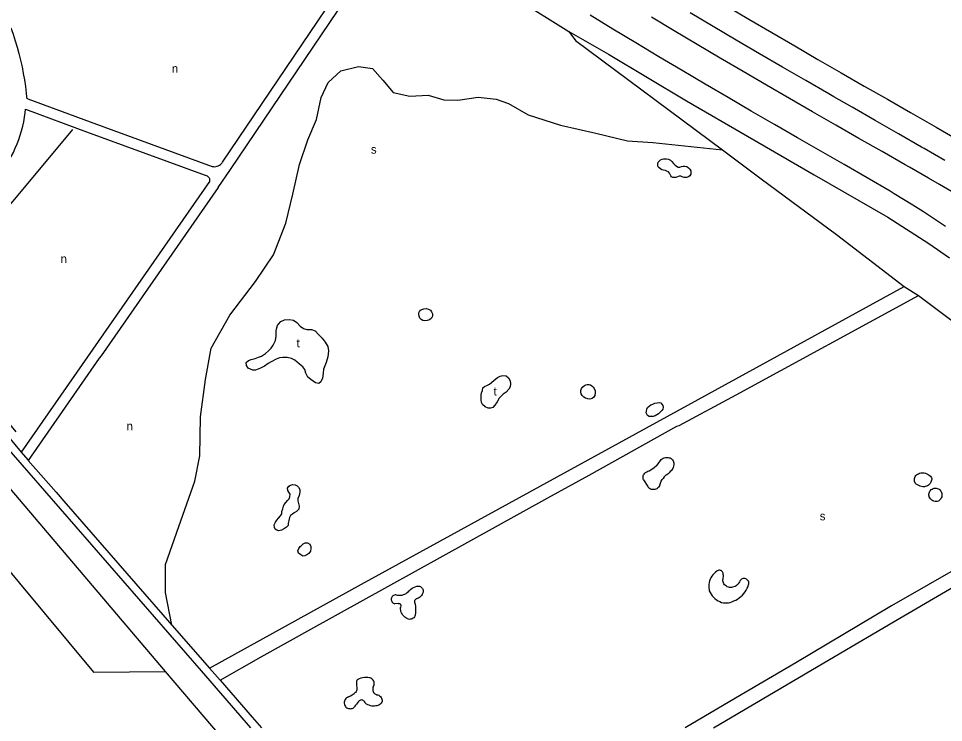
# Model space of a CAD drawing. Extents: x 156066 to 157805, y 383432 to 385631.
# Drawn here: x 156957.2 to 157390.3, y 384502.5 to 384832 of the extents above; entities that cross this region are included whole.
import ezdxf

# ---------------------------------------------------------------- set-up
doc = ezdxf.new("R2010")
doc.units = 0
doc.layers.add('BLT_Basislijn', color=7, linetype='Continuous')
doc.layers.add('BLT_Centroide', color=7, linetype='Continuous')

msp = doc.modelspace()

# ---------------------------------------------------------------- linework, layer by layer
at = {"layer": 'BLT_Basislijn'}
for p, q in [((157052.72, 384764.82), (157125.74, 384872.85)), ((157056.42, 384761.37), (157132.55, 384873.99)), ((156961.42, 384794.55), (156961.61, 384794.45)), ((157050.76, 384752.88), (157056.42, 384761.37)), ((157046.66, 384755.73), (156958.49, 384629.07)), ((157050.76, 384752.88), (156995.97, 384674.17)), ((157371.83, 384706.57), (157378.55, 384702.32)), ((156919.84, 384675.3), (156958.49, 384629.07)), ((156995.97, 384674.17), (156995.06, 384673.02)), ((156995.06, 384673.02), (156961.82, 384625.1)), ((156945.58, 384638.24), (157042.7, 384526.65)), ((156958.49, 384629.07), (156961.59, 384625.36)), ((156961.59, 384625.36), (156961.82, 384625.1)), ((156961.82, 384625.1), (156974.79, 384610.24)), ((157483.49, 384624.52), (157365.92, 384557.05)), ((157249.83, 384616.05), (157251.8, 384612.89)), ((156974.79, 384610.24), (156978.39, 384606.11)), ((156978.39, 384606.11), (157029.07, 384548.06)), ((157287.16, 384571.65), (157286.96, 384569.46)), ((157134.89, 384558.16), (157133.42, 384558.1)), ((157136.18, 384557.2), (157136.13, 384556.24)), ((157029.07, 384548.06), (157046.66, 384527.91)), ((157052.19, 384495.7), (157026.05, 384526.43)), ((157042.7, 384526.65), (157065.9, 384500)), ((157046.66, 384527.91), (157051.61, 384522.24)), ((157051.61, 384522.24), (157066.67, 384504.99)), ((157066.67, 384504.99), (157071.06, 384500))]:
    msp.add_line(p, q, dxfattribs=at)
for points in [[(157127.03, 384882.25), (157165.83, 384856.66), (157214.85, 384825.93)], [(157288.29, 384838.07), (157299.07, 384831.73), (157309.87, 384825.41), (157320.68, 384819.13), (157331.5, 384812.86), (157342.34, 384806.62), (157353.18, 384800.39), (157364.03, 384794.18), (157374.88, 384787.97), (157385.73, 384781.77), (157386.91, 384781.09), (157396.58, 384775.56)], [(157391.26, 384734.71), (157386.09, 384738.11), (157380.89, 384741.46), (157375.97, 384744.58), (157367.23, 384749.96), (157365.32, 384751.12), (157354.55, 384757.47), (157343.7, 384763.69), (157332.84, 384769.92), (157321.99, 384776.15), (157311.14, 384782.41), (157300.3, 384788.68), (157289.47, 384794.99), (157278.65, 384801.32), (157267.85, 384807.68), (157257.06, 384814.09), (157246.29, 384820.53), (157235.54, 384827.01), (157224.81, 384833.55)], [(157390.87, 384765.58), (157381.21, 384771.11), (157380.03, 384771.78), (157369.17, 384777.98), (157358.32, 384784.19), (157347.46, 384790.42), (157339, 384795.27), (157336.6, 384796.65), (157325.75, 384802.9), (157314.91, 384809.18), (157304.08, 384815.48), (157293.25, 384821.81), (157282.44, 384828.17), (157271.65, 384834.57)], [(157404.89, 384744.78), (157394.08, 384751.05), (157388.35, 384754.34), (157383.23, 384757.27), (157374.32, 384762.37), (157372.38, 384763.48), (157361.53, 384769.68), (157350.68, 384775.89), (157339.84, 384782.1), (157329, 384788.33), (157318.17, 384794.57), (157307.35, 384800.84), (157296.55, 384807.12), (157285.76, 384813.43), (157274.99, 384819.78), (157264.25, 384826.16), (157253.52, 384832.57)], [(156953.67, 384827.54), (156954.73, 384824.58), (156955.71, 384821.59), (156956.62, 384818.58), (156957.45, 384815.54), (156958.21, 384812.48), (156958.88, 384809.41), (156959.48, 384806.32), (156960, 384803.22), (156960.44, 384800.1), (156960.8, 384796.97), (156960.96, 384795.3)], [(157214.85, 384825.93), (157217.99, 384821.75), (157286.78, 384770.55)], [(157214.85, 384825.93), (157233.41, 384815.26), (157270.01, 384793.38), (157298.55, 384776.89), (157329.77, 384758.86), (157364.24, 384738.95), (157383.47, 384726.72), (157393.03, 384719.99)], [(157029.07, 384548.06), (157026.12, 384563.36), (157026.12, 384576.4), (157032.27, 384594.24), (157039.76, 384615.52), (157042.16, 384627.37), (157042.46, 384645.5), (157044.71, 384663.04), (157047.41, 384677.73), (157056.1, 384693.17), (157068.24, 384708.91), (157076.64, 384721.35), (157082.33, 384736.19), (157085.63, 384749.83), (157088.78, 384763.62), (157092.68, 384775.17), (157096.72, 384784.76), (157098.97, 384794.95), (157102.12, 384802), (157108.12, 384807.54), (157116.36, 384809.49), (157122.96, 384808.59), (157127.75, 384803.2), (157132.55, 384797.35), (157140.5, 384795.7), (157149.04, 384796.15), (157156.39, 384793.9), (157162.83, 384793.75), (157172.42, 384795.1), (157180.82, 384794.2), (157186.66, 384792.26), (157195.81, 384786.86), (157210.95, 384782.06), (157227.44, 384778.31), (157242.28, 384774.72), (157254.12, 384773.97), (157286.78, 384770.55)], [(156960.96, 384795.3), (156961.03, 384795.02), (156961.17, 384794.77), (156961.42, 384794.55)], [(156961.61, 384794.45), (156990.79, 384783.65), (157047.87, 384762.77)], [(156950.47, 384761.87), (156951.66, 384763.67), (156952.79, 384765.52), (156953.84, 384767.4), (156954.83, 384769.33), (156955.74, 384771.29), (156956.58, 384773.28), (156957.35, 384775.3), (156958.04, 384777.35), (156958.65, 384779.42), (156959.19, 384781.52), (156959.65, 384783.63), (156960.03, 384785.76), (156960.33, 384787.9), (156960.51, 384789.52)], [(156960.51, 384789.52), (156989.06, 384778.95), (157044.68, 384758.61)], [(156956.19, 384638.52), (156911.52, 384692.57), (156911.79, 384695.16), (156982.6, 384779.99)], [(157286.78, 384770.55), (157304.97, 384757.01), (157340.2, 384730.93), (157371.83, 384706.57)], [(157047.87, 384762.77), (157048.45, 384762.66), (157049.04, 384762.63), (157049.62, 384762.68), (157050.19, 384762.81), (157050.74, 384763.01), (157051.26, 384763.29), (157051.73, 384763.64), (157052.16, 384764.04), (157052.52, 384764.51), (157052.72, 384764.82)], [(157044.68, 384758.61), (157045.1, 384758.51), (157045.5, 384758.34), (157045.86, 384758.1), (157046.17, 384757.79), (157046.41, 384757.44), (157046.59, 384757.04), (157046.69, 384756.62), (157046.72, 384756.19), (157046.66, 384755.73)], [(157046.66, 384527.91), (157117.78, 384567.25), (157371.83, 384706.57)], [(157266.45, 384641.56), (157293.22, 384655.8), (157378.55, 384702.32)], [(157378.55, 384702.32), (157403.46, 384683.56), (157435.54, 384660.17), (157461.32, 384641.74), (157483.49, 384624.52)], [(157094.16, 384546.16), (157204.99, 384607.7), (157224.46, 384618.24), (157265.47, 384641.16), (157266.45, 384641.56)], [(157026.05, 384526.43), (156941.82, 384625.43), (156931.88, 384633.77)], [(157257.4, 384624.66), (157257.71, 384625.11), (157258.09, 384625.51), (157258.52, 384625.86), (157259, 384626.14), (157259.52, 384626.34), (157260.05, 384626.47), (157260.6, 384626.53), (157260.87, 384626.52)], [(157260.87, 384626.52), (157261.35, 384626.52), (157261.83, 384626.44), (157262.28, 384626.29), (157262.71, 384626.06), (157263.09, 384625.76), (157263.41, 384625.41), (157263.68, 384625), (157263.87, 384624.56), (157263.99, 384624.09), (157264.03, 384623.72)], [(156910.63, 384624.14), (156992.3, 384525.98), (157026.05, 384526.43)], [(157252.48, 384620.3), (157253.67, 384621.06), (157254.83, 384621.88), (157255.94, 384622.76), (157256.15, 384622.95)], [(157256.15, 384622.95), (157256.94, 384623.98), (157257.4, 384624.66)], [(157264.03, 384623.72), (157264.01, 384623.11), (157263.91, 384622.5), (157263.73, 384621.91), (157263.48, 384621.34), (157263.16, 384620.81), (157262.77, 384620.33), (157262.37, 384619.94)], [(157249.83, 384616.05), (157249.68, 384616.5), (157249.6, 384616.97), (157249.61, 384617.45), (157249.69, 384617.92), (157249.85, 384618.37), (157250.08, 384618.78), (157250.38, 384619.15), (157250.82, 384619.53)], [(157250.82, 384619.53), (157251.33, 384619.85), (157251.87, 384620.11), (157252.48, 384620.3)], [(157260.19, 384618.07), (157259.55, 384617.43), (157258.97, 384616.74), (157258.69, 384616.36)], [(157262.37, 384619.94), (157261.79, 384619.32), (157261.15, 384618.75), (157260.45, 384618.24), (157260.19, 384618.07)], [(157377.18, 384614.32), (157376.93, 384614.75), (157376.75, 384615.21), (157376.65, 384615.7), (157376.63, 384616.2), (157376.69, 384616.69), (157376.83, 384617.17), (157377.04, 384617.62), (157377.33, 384618.03), (157377.67, 384618.39), (157378.04, 384618.67)], [(157378.04, 384618.67), (157378.53, 384618.95), (157379.06, 384619.16), (157379.62, 384619.3), (157380.18, 384619.35), (157380.53, 384619.34)], [(157380.53, 384619.34), (157381.19, 384619.27), (157381.84, 384619.12), (157382.46, 384618.89), (157383.06, 384618.59), (157383.62, 384618.22), (157384.12, 384617.78), (157384.57, 384617.29), (157384.69, 384617.14)], [(157384.69, 384617.14), (157384.77, 384616.71), (157384.78, 384616.27), (157384.7, 384615.84), (157384.55, 384615.42)], [(157253.98, 384611.54), (157253.52, 384611.61), (157253.07, 384611.76), (157252.66, 384611.98), (157252.3, 384612.27), (157251.99, 384612.62), (157251.8, 384612.89)], [(157257.4, 384613.72), (157257.26, 384613.27), (157257.05, 384612.84), (157256.77, 384612.45), (157256.43, 384612.12), (157256.04, 384611.85), (157255.61, 384611.65), (157255.15, 384611.52), (157254.68, 384611.47), (157254.2, 384611.5), (157253.98, 384611.54)], [(157257.4, 384613.72), (157257.72, 384614.58), (157258.11, 384615.4), (157258.58, 384616.19), (157258.69, 384616.36)], [(157381.34, 384612.83), (157380.65, 384612.84), (157379.97, 384612.93), (157379.3, 384613.11), (157378.66, 384613.35), (157378.05, 384613.67), (157377.49, 384614.06), (157377.18, 384614.32)], [(157384.55, 384615.42), (157384.32, 384614.9), (157384.02, 384614.42), (157383.65, 384613.99), (157383.23, 384613.62), (157382.76, 384613.31), (157382.25, 384613.07), (157381.71, 384612.9), (157381.34, 384612.83)], [(157383.54, 384608.38), (157383.45, 384608.86), (157383.44, 384609.35), (157383.52, 384609.84), (157383.66, 384610.31), (157383.89, 384610.75), (157384.18, 384611.14), (157384.53, 384611.49), (157384.93, 384611.77), (157385.37, 384611.99), (157385.84, 384612.12), (157386.33, 384612.19), (157386.82, 384612.17), (157387.3, 384612.07), (157387.77, 384611.9), (157388.19, 384611.65), (157388.57, 384611.34), (157388.9, 384610.97), (157389.14, 384610.58)], [(157387.32, 384605.93), (157386.81, 384605.89), (157386.29, 384605.93), (157385.78, 384606.05), (157385.3, 384606.24), (157384.86, 384606.51), (157384.46, 384606.84), (157384.11, 384607.22), (157383.83, 384607.66), (157383.62, 384608.14), (157383.54, 384608.38)], [(157389.14, 384610.58), (157389.35, 384610.11), (157389.48, 384609.62), (157389.54, 384609.11), (157389.51, 384608.6), (157389.41, 384608.1), (157389.23, 384607.63), (157388.97, 384607.18), (157388.65, 384606.79), (157388.27, 384606.44), (157387.85, 384606.16), (157387.32, 384605.93)], [(157336.87, 384531.91), (157369.89, 384551.32), (157453.47, 384600.17)], [(157287.16, 384571.65), (157287.18, 384572.03), (157287.12, 384572.41), (157286.99, 384572.77), (157286.78, 384573.08), (157286.51, 384573.35), (157286.19, 384573.56), (157285.83, 384573.7), (157285.46, 384573.76), (157285.08, 384573.74), (157284.71, 384573.64), (157284.37, 384573.46), (157284.12, 384573.27)], [(157284.12, 384573.27), (157283.46, 384572.79), (157282.85, 384572.24), (157282.3, 384571.63), (157281.81, 384570.97), (157281.38, 384570.27), (157281.02, 384569.53), (157280.74, 384568.76), (157280.54, 384567.96), (157280.41, 384567.15), (157280.36, 384566.33), (157280.39, 384565.51), (157280.51, 384564.7), (157280.64, 384564.11)], [(157290.08, 384565.73), (157289.56, 384565.82), (157289.06, 384565.99), (157288.6, 384566.24), (157288.17, 384566.55), (157287.8, 384566.92), (157287.48, 384567.35), (157287.24, 384567.81), (157287.07, 384568.31), (157286.97, 384568.83), (157286.96, 384569.36), (157286.96, 384569.46)], [(157298.88, 384566.54), (157299.04, 384566.93), (157299.13, 384567.35), (157299.14, 384567.77), (157299.07, 384568.19), (157298.92, 384568.59), (157298.7, 384568.95), (157298.41, 384569.27), (157298.07, 384569.52), (157297.69, 384569.71), (157297.28, 384569.83), (157296.86, 384569.86), (157296.44, 384569.82), (157296.03, 384569.7), (157295.65, 384569.5), (157295.32, 384569.24), (157295.03, 384568.89)], [(157139.84, 384563.91), (157140.36, 384564.46), (157140.93, 384564.95), (157141.56, 384565.38), (157142.22, 384565.74), (157142.92, 384566.04), (157143.73, 384566.27)], [(157143.73, 384566.27), (157144.16, 384566.35), (157144.59, 384566.34), (157145.02, 384566.26), (157145.42, 384566.1), (157145.79, 384565.86), (157146.1, 384565.57), (157146.36, 384565.22), (157146.55, 384564.83), (157146.67, 384564.41), (157146.7, 384563.98), (157146.66, 384563.55), (157146.54, 384563.13), (157146.43, 384562.89)], [(157295.03, 384568.89), (157294.8, 384568.33), (157294.5, 384567.8), (157294.14, 384567.31), (157293.71, 384566.88), (157293.23, 384566.5), (157292.7, 384566.19), (157292.14, 384565.96), (157291.55, 384565.79), (157290.95, 384565.71), (157290.34, 384565.71), (157290.08, 384565.73)], [(157292.11, 384559.36), (157293, 384559.77), (157293.86, 384560.26), (157294.67, 384560.81), (157295.43, 384561.43), (157296.14, 384562.1), (157296.8, 384562.83), (157297.39, 384563.61), (157297.92, 384564.44), (157298.38, 384565.31), (157298.76, 384566.22), (157298.88, 384566.54)], [(157134.04, 384562.22), (157133.64, 384562.22), (157133.24, 384562.15), (157132.86, 384562), (157132.51, 384561.78), (157132.22, 384561.5), (157131.99, 384561.16), (157131.83, 384560.79), (157131.74, 384560.39), (157131.73, 384559.98), (157131.8, 384559.58), (157131.95, 384559.2), (157132.17, 384558.86), (157132.46, 384558.57), (157132.79, 384558.33), (157133.16, 384558.17), (157133.42, 384558.1)], [(157134.04, 384562.22), (157134.72, 384562.08), (157135.4, 384562.03), (157136.09, 384562.06), (157136.77, 384562.16), (157137.43, 384562.35), (157138.07, 384562.61), (157138.67, 384562.94), (157139.23, 384563.34), (157139.74, 384563.8), (157139.84, 384563.91)], [(157146.43, 384562.89), (157146.17, 384562.36), (157145.83, 384561.88), (157145.43, 384561.44), (157144.98, 384561.06), (157144.48, 384560.75), (157143.94, 384560.5), (157143.67, 384560.41)], [(157280.64, 384564.11), (157281.03, 384563.3), (157281.49, 384562.54), (157282.02, 384561.82), (157282.6, 384561.15), (157283.25, 384560.53), (157283.95, 384559.98), (157284.7, 384559.49), (157285.48, 384559.07), (157286.3, 384558.72), (157286.43, 384558.67)], [(157134.89, 384558.16), (157135.15, 384558.24), (157135.42, 384558.23), (157135.68, 384558.15), (157135.9, 384558), (157136.07, 384557.79), (157136.17, 384557.54), (157136.18, 384557.2)], [(157143.67, 384560.41), (157143.36, 384560.3), (157143.08, 384560.11), (157142.85, 384559.86), (157142.68, 384559.56), (157142.6, 384559.24), (157142.59, 384558.9), (157142.6, 384558.78)], [(157142.6, 384558.78), (157142.85, 384557.8), (157143.01, 384556.81), (157143.1, 384555.8), (157143.1, 384554.8), (157143.03, 384553.79), (157142.88, 384552.8), (157142.77, 384552.3)], [(157286.43, 384558.67), (157287.21, 384558.51), (157288, 384558.43), (157288.79, 384558.43), (157289.58, 384558.52), (157290.36, 384558.68), (157291.11, 384558.91), (157291.84, 384559.22), (157292.11, 384559.36)], [(157365.92, 384557.05), (157321.18, 384530.45), (157292.9, 384513.83)], [(157136.18, 384554.95), (157136.12, 384555.77), (157136.13, 384556.24)], [(157139.11, 384551.12), (157138.54, 384551.43), (157138.02, 384551.81), (157137.55, 384552.25), (157137.13, 384552.75), (157136.78, 384553.29), (157136.49, 384553.87), (157136.29, 384554.49), (157136.18, 384554.95)], [(157142.77, 384552.3), (157142.55, 384551.9), (157142.26, 384551.55), (157141.92, 384551.25), (157141.53, 384551.02), (157141.11, 384550.86), (157140.66, 384550.78), (157140.21, 384550.77), (157139.76, 384550.85), (157139.33, 384551), (157139.11, 384551.12)], [(157051.61, 384522.24), (157070.77, 384533.17), (157094.16, 384546.16)], [(157282.62, 384500), (157336.87, 384531.91)], [(157116.68, 384522.96), (157116.34, 384522.84), (157116.04, 384522.65), (157115.79, 384522.4), (157115.59, 384522.1), (157115.47, 384521.76), (157115.43, 384521.41), (157115.46, 384521.09)], [(157121.58, 384523.4), (157120.77, 384523.53), (157119.95, 384523.58), (157119.13, 384523.55), (157118.32, 384523.44), (157117.52, 384523.25), (157116.68, 384522.96)], [(157123.33, 384519.18), (157123.55, 384519.6), (157123.7, 384520.04), (157123.78, 384520.5), (157123.77, 384520.97), (157123.69, 384521.43), (157123.52, 384521.87), (157123.29, 384522.28), (157122.99, 384522.64), (157122.63, 384522.95), (157122.23, 384523.18), (157121.79, 384523.35), (157121.58, 384523.4)], [(157115.54, 384519.02), (157115.64, 384518.6), (157115.65, 384518.16), (157115.59, 384517.73), (157115.45, 384517.32), (157115.23, 384516.94), (157114.95, 384516.6), (157114.62, 384516.32), (157114.53, 384516.27)], [(157115.46, 384521.09), (157115.42, 384519.71), (157115.54, 384519.02)], [(157123.33, 384519.18), (157123.16, 384518.76), (157123.06, 384518.32), (157123.05, 384517.86), (157123.12, 384517.41), (157123.26, 384516.98), (157123.48, 384516.57), (157123.76, 384516.22), (157124.1, 384515.92), (157124.49, 384515.68), (157124.92, 384515.51), (157125.43, 384515.41)], [(157111.69, 384514.44), (157111.25, 384514.25), (157110.85, 384513.99), (157110.49, 384513.67), (157110.19, 384513.3), (157109.96, 384512.87), (157109.8, 384512.42), (157109.72, 384511.95), (157109.72, 384511.47), (157109.79, 384510.99), (157109.83, 384510.87)], [(157111.69, 384514.44), (157112.61, 384514.92), (157113.48, 384515.47), (157114.31, 384516.08), (157114.53, 384516.27)], [(157125.43, 384515.41), (157125.88, 384515.23), (157126.29, 384514.97), (157126.65, 384514.65), (157126.96, 384514.27), (157127.2, 384513.85), (157127.36, 384513.39), (157127.45, 384512.91), (157127.46, 384512.45)], [(157292.9, 384513.83), (157269.37, 384500)], [(157109.83, 384510.87), (157110, 384510.44), (157110.24, 384510.05), (157110.54, 384509.7), (157110.9, 384509.41), (157111.3, 384509.19), (157111.74, 384509.04), (157112.2, 384508.97), (157112.46, 384508.96)], [(157112.46, 384508.96), (157112.93, 384508.98), (157113.4, 384509.08), (157113.84, 384509.26), (157114.24, 384509.5), (157114.6, 384509.82), (157114.9, 384510.18), (157115.14, 384510.59), (157115.26, 384510.91)], [(157116.43, 384512.33), (157115.89, 384511.76), (157115.41, 384511.13), (157115.26, 384510.91)], [(157119.43, 384511.8), (157119.29, 384512.14), (157119.08, 384512.45), (157118.81, 384512.7), (157118.49, 384512.88), (157118.14, 384512.99), (157117.78, 384513.03), (157117.41, 384512.98), (157117.07, 384512.86), (157116.75, 384512.66), (157116.43, 384512.33)], [(157124.54, 384510.3), (157123.9, 384510.19), (157123.25, 384510.16), (157122.6, 384510.2), (157121.96, 384510.33), (157121.33, 384510.53), (157120.74, 384510.8), (157120.19, 384511.15), (157119.68, 384511.56), (157119.43, 384511.8)], [(157127.46, 384512.45), (157127.29, 384512), (157127.05, 384511.58), (157126.74, 384511.2), (157126.37, 384510.88), (157125.96, 384510.62), (157125.51, 384510.44), (157125.03, 384510.33), (157124.54, 384510.3)]]:
    msp.add_lwpolyline(points, dxfattribs=at)
for points in [[(157259.67, 384766.36), (157260.64, 384766.34), (157261.47, 384766.15), (157262.4, 384765.72), (157263.15, 384765.05), (157263.88, 384764.06), (157264.58, 384763.29), (157265.25, 384762.82), (157265.98, 384762.48), (157266.86, 384762.48), (157267.63, 384762.67), (157268.36, 384762.87), (157269.22, 384762.87), (157270.08, 384762.65), (157270.91, 384762.14), (157271.53, 384761.43), (157271.92, 384760.63), (157272.01, 384759.88), (157271.98, 384759.11), (157271.51, 384758.4), (157270.82, 384757.83), (157269.88, 384757.52), (157268.79, 384757.57), (157268, 384757.83), (157267.33, 384758.17), (157266.47, 384758.23), (157265.76, 384757.93), (157264.99, 384757.63), (157264.22, 384757.52), (157263.53, 384757.53), (157262.98, 384757.83), (157262.63, 384758.4), (157262.33, 384759), (157262.05, 384759.61), (157261.48, 384760.16), (157260.79, 384760.55), (157260.1, 384760.83), (157259.25, 384761.02), (157258.45, 384761.21), (157257.77, 384761.56), (157257.17, 384762.09), (157256.74, 384762.63), (157256.48, 384763.34), (157256.48, 384763.91), (157256.65, 384764.71), (157257.08, 384765.29), (157257.77, 384765.78), (157258.58, 384766.12), (157259.22, 384766.34)], [(157146.06, 384695.79), (157147.05, 384696.13), (157148.05, 384696.21), (157149.15, 384696), (157150.03, 384695.4), (157150.61, 384694.63), (157150.97, 384693.7), (157151.01, 384692.65), (157150.5, 384691.8), (157149.58, 384691), (157148.61, 384690.57), (157147.48, 384690.49), (157146.49, 384690.59), (157145.74, 384691.05), (157145.07, 384691.8), (157144.75, 384692.61), (157144.58, 384693.38), (157144.64, 384694.2), (157144.92, 384694.91), (157145.4, 384695.42)], [(157079, 384688.9), (157080.09, 384690.21), (157081.7, 384691), (157083.98, 384691.07), (157085.93, 384690.74), (157087.58, 384689.69), (157089.04, 384687.92), (157090.58, 384686.91), (157092.15, 384686.5), (157094.36, 384686.46), (157096.05, 384685.86), (157097.7, 384684.14), (157099.46, 384682.38), (157100.77, 384680.54), (157102.01, 384678.52), (157102.38, 384676.38), (157102.08, 384673.65), (157101.22, 384670.99), (157100.02, 384667.84), (157099.84, 384665.96), (157099.54, 384663.68), (157098.75, 384661.99), (157097.81, 384661.17), (157096.24, 384661.54), (157094.14, 384662.97), (157092.75, 384664.13), (157091.78, 384665.93), (157091.33, 384667.69), (157090.32, 384668.92), (157088.82, 384670.24), (157086.64, 384672.11), (157085, 384672.93), (157083.01, 384673.27), (157081.02, 384673.27), (157079.45, 384673.16), (157077.91, 384672.52), (157075.59, 384671.25), (157074.09, 384670.57), (157072.37, 384669.3), (157070.57, 384668.4), (157068.17, 384667.46), (157066.93, 384667.43), (157064.76, 384668.33), (157063.93, 384669.56), (157063.78, 384670.95), (157064.83, 384671.85), (157066.22, 384672.34), (157068.06, 384672.82), (157069.63, 384673.53), (157070.94, 384674.02), (157072.82, 384675.18), (157074.31, 384676.49), (157075.51, 384677.62), (157076.49, 384679.08), (157077.5, 384681.25), (157077.84, 384683.35), (157077.91, 384685.83), (157078.23, 384687.16), (157078.55, 384688.24)], [(157177.65, 384660.91), (157179.71, 384662.59), (157181.4, 384663.94), (157182.79, 384664.65), (157183.95, 384664.84), (157185.56, 384664.77), (157186.65, 384663.83), (157187.36, 384662.44), (157187.62, 384660.98), (157187.4, 384659.63), (157186.83, 384658.51), (157185.52, 384657.16), (157184.06, 384656.18), (157183.24, 384655.21), (157182.3, 384654.27), (157181.25, 384652.62), (157180.2, 384650.94), (157179.3, 384650), (157178.25, 384649.59), (157177.13, 384649.59), (157175.67, 384650.3), (157174.47, 384651.31), (157174.02, 384652.32), (157173.75, 384653.56), (157173.79, 384654.57), (157173.9, 384655.7), (157174.02, 384656.82), (157174.39, 384657.83), (157174.54, 384659.07), (157175.37, 384659.78), (157176.75, 384660.42)], [(157223.5, 384660.66), (157224.33, 384660.74), (157225.06, 384660.55), (157225.66, 384660.14), (157226.24, 384659.5), (157226.78, 384658.79), (157227.18, 384657.79), (157227.23, 384656.88), (157227.04, 384655.55), (157226.54, 384654.76), (157225.73, 384654.18), (157224.7, 384653.88), (157223.75, 384653.92), (157222.7, 384654.25), (157221.82, 384654.8), (157221.07, 384655.58), (157220.65, 384656.3), (157220.52, 384657.05), (157220.5, 384657.94), (157220.73, 384658.84), (157221.35, 384659.63), (157222.19, 384660.29), (157222.9, 384660.59)], [(157254.12, 384651.5), (157255.11, 384651.93), (157256.16, 384652.14), (157257.17, 384652.21), (157257.92, 384652.08), (157258.45, 384651.5), (157258.82, 384650.9), (157258.95, 384650.13), (157258.84, 384649.12), (157258.37, 384648.46), (157257.66, 384647.7), (157256.78, 384646.96), (157256.05, 384646.48), (157255.21, 384646.05), (157254.29, 384645.75), (157253.28, 384645.65), (157252.4, 384645.78), (157251.7, 384646.21), (157251.35, 384646.74), (157251.14, 384647.49), (157251.16, 384648.26), (157251.35, 384649.08), (157251.76, 384649.87), (157252.41, 384650.58), (157253.2, 384651.11)], [(157083.83, 384613.05), (157084.55, 384613.65), (157085.67, 384613.91), (157086.68, 384613.8), (157087.69, 384613.27), (157088.26, 384612.64), (157088.86, 384611.59), (157088.97, 384610.24), (157088.63, 384608.74), (157088.07, 384607.35), (157088.03, 384606.3), (157088.37, 384605.03), (157088.63, 384603.68), (157088.44, 384602.37), (157087.43, 384601.24), (157086.31, 384600.65), (157085.44, 384599.93), (157084.55, 384599.37), (157084.1, 384598.47), (157083.72, 384597.05), (157083.5, 384595.85), (157083.42, 384594.76), (157082.75, 384593.94), (157081.77, 384593.26), (157080.35, 384592.48), (157079.11, 384592.25), (157078.1, 384592.44), (157077.43, 384593), (157077.01, 384593.79), (157076.98, 384595.02), (157077.54, 384596.19), (157078.14, 384597.16), (157078.92, 384598.13), (157079.86, 384599.26), (157080.5, 384600.23), (157080.5, 384601.17), (157080.91, 384602.52), (157081.29, 384603.72), (157081.62, 384604.51), (157082.48, 384605.55), (157083.2, 384606.38), (157083.95, 384607.13), (157084.32, 384608.07), (157084.4, 384609.3), (157083.8, 384610.28), (157083.27, 384611.03), (157083.23, 384612.15)], [(157089.53, 384585.24), (157090.47, 384586.14), (157091.37, 384586.52), (157092.57, 384586.63), (157093.54, 384586.03), (157094.1, 384584.94), (157094.06, 384583.89), (157093.91, 384582.69), (157093.09, 384581.65), (157092.19, 384580.97), (157091.25, 384580.45), (157090.32, 384580.41), (157089.34, 384580.93), (157088.29, 384581.8), (157088.07, 384582.84), (157088.41, 384583.89), (157089.04, 384584.83)]]:
    msp.add_lwpolyline(points, close=True, dxfattribs=at)

# ---------------------------------------------------------------- texts
at = {"layer": 'BLT_Centroide'}
for s, p in [('n', (157029, 384806.59)), ('s', (157122.21, 384768.72)), ('n', (156976.93, 384717.53)), ('t', (157087.39, 384678.11)), ('t', (157179.64, 384655.55)), ('n', (157007.82, 384639.23)), ('s', (157332.34, 384597.13))]:
    msp.add_text(s, height=4, dxfattribs=at).set_placement(p)

doc.saveas('drawing.dxf')
